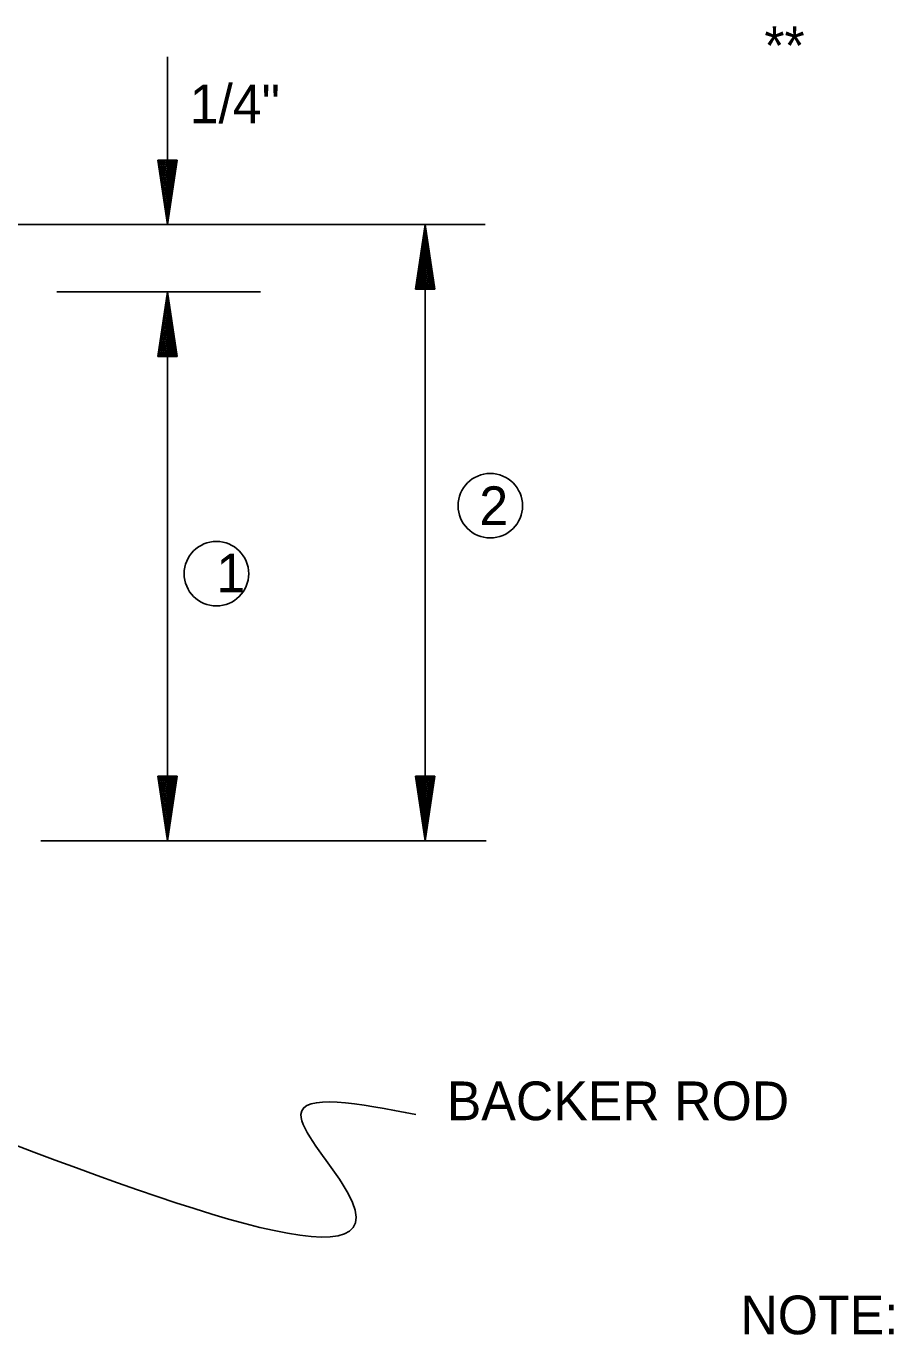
# Model space of a CAD drawing. Extents: x 1375738 to 1375905, y 380661 to 380875.
# Drawn here: x 1375851.88 to 1375865.33, y 380705.05 to 380725.34 of the extents above; entities that cross this region are included whole.
import ezdxf

# ---------------------------------------------------------------- set-up
doc = ezdxf.new("R2010")
doc.units = 0
doc.layers.add('R_Draft', color=7, linetype='Continuous')

msp = doc.modelspace()

# ---------------------------------------------------------------- linework, layer by layer
at = {"layer": 'R_Draft'}
for p, q in [((1375854.068, 380724.865), (1375854.068, 380722.262)), ((1375853.918, 380723.262), (1375854.068, 380722.262)), ((1375854.218, 380723.262), (1375853.918, 380723.262)), ((1375853.943, 380723.262), (1375854.068, 380722.429)), ((1375853.968, 380723.262), (1375854.068, 380722.601)), ((1375853.993, 380723.262), (1375854.068, 380722.767)), ((1375854.019, 380723.262), (1375854.068, 380722.937)), ((1375854.044, 380723.262), (1375854.068, 380723.104)), ((1375854.218, 380723.262), (1375854.068, 380722.262)), ((1375854.116, 380723.262), (1375854.068, 380722.937)), ((1375854.167, 380723.262), (1375854.068, 380722.601)), ((1375854.193, 380723.262), (1375854.068, 380722.429)), ((1375854.142, 380723.262), (1375854.068, 380722.767)), ((1375854.091, 380723.262), (1375854.068, 380723.104)), ((1375851.607, 380722.262), (1375858.991, 380722.262)), ((1375857.913, 380721.262), (1375858.063, 380722.262)), ((1375858.063, 380722.262), (1375858.063, 380712.708)), ((1375858.213, 380721.262), (1375858.063, 380722.262)), ((1375857.938, 380721.262), (1375858.063, 380722.095)), ((1375858.188, 380721.262), (1375858.063, 380722.095)), ((1375857.964, 380721.262), (1375858.063, 380721.923)), ((1375858.163, 380721.262), (1375858.063, 380721.923)), ((1375857.989, 380721.262), (1375858.063, 380721.756)), ((1375858.138, 380721.262), (1375858.063, 380721.756)), ((1375858.015, 380721.262), (1375858.063, 380721.587)), ((1375858.112, 380721.262), (1375858.063, 380721.587)), ((1375857.913, 380721.262), (1375858.213, 380721.262)), ((1375858.04, 380721.262), (1375858.063, 380721.42)), ((1375858.087, 380721.262), (1375858.063, 380721.42)), ((1375852.356, 380721.218), (1375855.513, 380721.218)), ((1375853.918, 380720.218), (1375854.068, 380721.218)), ((1375853.943, 380720.218), (1375854.068, 380721.051)), ((1375854.218, 380720.218), (1375854.068, 380721.218)), ((1375854.068, 380721.218), (1375854.068, 380712.708)), ((1375854.193, 380720.218), (1375854.068, 380721.051)), ((1375853.968, 380720.218), (1375854.068, 380720.879)), ((1375854.167, 380720.218), (1375854.068, 380720.879)), ((1375853.993, 380720.218), (1375854.068, 380720.713)), ((1375854.142, 380720.218), (1375854.068, 380720.713)), ((1375854.019, 380720.218), (1375854.068, 380720.543)), ((1375854.117, 380720.218), (1375854.068, 380720.543)), ((1375854.044, 380720.218), (1375854.068, 380720.376)), ((1375854.091, 380720.218), (1375854.068, 380720.376)), ((1375853.918, 380720.218), (1375854.218, 380720.218)), ((1375853.918, 380713.708), (1375854.068, 380712.708)), ((1375854.218, 380713.708), (1375853.918, 380713.708)), ((1375853.943, 380713.708), (1375854.068, 380712.875)), ((1375853.968, 380713.708), (1375854.068, 380713.047)), ((1375853.993, 380713.708), (1375854.068, 380713.213)), ((1375854.019, 380713.708), (1375854.068, 380713.383)), ((1375854.044, 380713.708), (1375854.068, 380713.55)), ((1375854.218, 380713.708), (1375854.068, 380712.708)), ((1375854.116, 380713.708), (1375854.068, 380713.383)), ((1375854.167, 380713.708), (1375854.068, 380713.047)), ((1375854.193, 380713.708), (1375854.068, 380712.875)), ((1375854.142, 380713.708), (1375854.068, 380713.213)), ((1375854.091, 380713.708), (1375854.068, 380713.55)), ((1375857.913, 380713.708), (1375858.063, 380712.708)), ((1375858.213, 380713.708), (1375857.913, 380713.708)), ((1375857.938, 380713.708), (1375858.063, 380712.875)), ((1375857.964, 380713.708), (1375858.063, 380713.047)), ((1375857.989, 380713.708), (1375858.063, 380713.213)), ((1375858.014, 380713.708), (1375858.063, 380713.383)), ((1375858.04, 380713.708), (1375858.063, 380713.55)), ((1375858.213, 380713.708), (1375858.063, 380712.708)), ((1375858.112, 380713.708), (1375858.063, 380713.383)), ((1375858.163, 380713.708), (1375858.063, 380713.047)), ((1375858.188, 380713.708), (1375858.063, 380712.875)), ((1375858.138, 380713.708), (1375858.063, 380713.213)), ((1375858.087, 380713.708), (1375858.063, 380713.55)), ((1375852.106, 380712.708), (1375859.01, 380712.708))]:
    msp.add_line(p, q, dxfattribs=at)
for centre in [(1375859.072, 380717.903), (1375854.828, 380716.849)]:
    msp.add_circle(centre, 0.5, dxfattribs=at)
msp.add_spline([(1375857.92, 380708.464), (1375856.137, 380708.464), (1375856.779, 380707.394), (1375850.643, 380708.393)], degree=3, dxfattribs=at)

# ---------------------------------------------------------------- texts
for s, p in [('**', (1375863.319, 380724.739)), ('1/4"', (1375854.413, 380723.834)), ('2', (1375858.902, 380717.603)), ('1', (1375854.828, 380716.56)), ('BACKER ROD', (1375858.398, 380708.375)), ('NOTE:', (1375862.947, 380705.055))]:
    msp.add_text(s, height=0.6, dxfattribs=at).set_placement(p)

doc.saveas('drawing.dxf')
